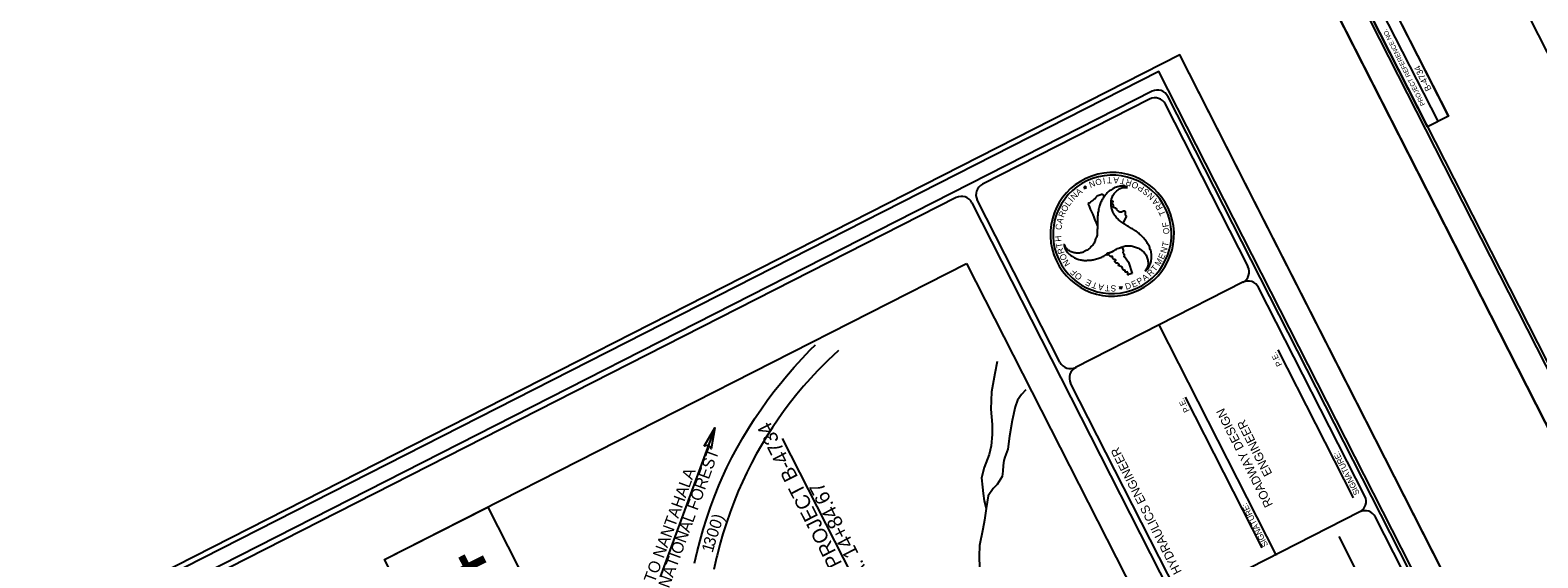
# Model space of a CAD drawing. Extents: x 558484 to 564063, y 513718 to 518374.
# Drawn here: x 558646 to 559932, y 515996 to 516446 of the extents above; entities that cross this region are included whole.
import ezdxf

# ---------------------------------------------------------------- set-up
doc = ezdxf.new("R2010")
doc.units = 0
for name, color, linetype in [('Default', 7, 'Continuous'), ('Prop DSN Text', 7, 'Continuous'), ('Prop Terminator CELL', 7, 'Continuous'), ('Sheet Cutting Line CELL', 7, 'Continuous'), ('Sheet Data Field CELL', 7, 'Continuous'), ('Sheet Plot Border Inside CELL', 7, 'Continuous'), ('Sheet Plot Border Outside CELL', 7, 'Continuous'), ('Sheet Symbology CELL', 7, 'Continuous'), ('Sheet Title CELL', 7, 'Continuous')]:
    doc.layers.add(name, color=color, linetype=linetype)

msp = doc.modelspace()

# ---------------------------------------------------------------- linework, layer by layer
at = {"layer": 'Default'}
msp.add_line((559230, 516106.5), (559183.4, 515979.3), dxfattribs=at)
for points in [[(559444.5, 516246.6), (559867.2, 515416.2), (559371.1, 515163.6), (558948.4, 515994)], [(559036.3, 516038.8), (559079.2, 515954.4), (558991.3, 515909.7), (558948.4, 515994)]]:
    msp.add_lwpolyline(points, close=True, dxfattribs=at)
for points in [[(559212.5, 515991), (559214.8, 516000.7), (559217.3, 516010.3), (559220.1, 516019.8), (559223, 516029.3), (559226.2, 516038.7), (559229.7, 516048), (559233.3, 516057.2), (559236.1, 516063.9), (559240.2, 516072.5), (559244.5, 516081.1), (559249, 516089.5), (559253.7, 516097.8), (559258.6, 516105.9), (559263.8, 516114), (559269.1, 516121.9), (559274.6, 516129.7), (559280.3, 516137.3), (559284.7, 516142.9), (559291.1, 516150.6), (559297.6, 516158.2), (559304.3, 516165.6), (559311.2, 516172.8), (559315.7, 516177.3)], [(559335.3, 516172.3), (559326.2, 516163.7), (559323.6, 516161.3), (559317.4, 516155), (559311.4, 516148.5), (559305.6, 516141.9), (559299.9, 516135.1), (559294.4, 516128.2), (559289.1, 516121.1), (559284, 516113.9), (559279.1, 516106.6), (559274.3, 516099.2), (559269.7, 516091.6), (559265.3, 516083.9), (559261.1, 516076.2), (559257.1, 516068.3), (559253.4, 516060.3), (559249.9, 516052.4), (559246.3, 516043.5), (559243, 516034.4), (559239.8, 516025.3), (559236.9, 516016.1), (559234.2, 516006.9), (559231.8, 515997.6), (559231.4, 515995.9), (559229, 515985.6)], [(559470.6, 516163), (559468.8, 516152.8), (559465.8, 516137.2), (559465.4, 516122.3), (559466.4, 516109.4), (559466.4, 516100.7), (559465.7, 516091.2), (559463.8, 516083.8), (559459.6, 516072.7), (559457.4, 516063.9), (559458.2, 516055.9), (559458.8, 516050.4), (559459.5, 516044.2), (559461.2, 516037.6), (559459.9, 516027.8), (559458.5, 516020.1), (559455.7, 516006.2), (559455.3, 515996.9), (559455.7, 515987)], [(559495.2, 516138.7), (559491.5, 516134.9), (559488.1, 516129.9), (559486, 516124.4), (559483.4, 516112.7), (559481.3, 516099.2), (559479.9, 516088.2), (559477.3, 516081.3), (559476.4, 516078.7), (559475.7, 516074.4), (559475.4, 516069.5), (559474.9, 516064.8), (559470.8, 516058.2), (559467.4, 516054.6), (559462.9, 516048.3), (559461.2, 516037.6)]]:
    msp.add_lwpolyline(points, dxfattribs=at)
at = {"layer": 'Prop DSN Text'}
msp.add_line((559374.5, 515926.8), (559287.7, 516097.2), dxfattribs=at)
at = {"layer": 'Prop Terminator CELL'}
msp.add_lwpolyline([(559220.9, 516090.7), (559230, 516106.5), (559226.8, 516088.4), (559224.6, 516091.7)], close=True, dxfattribs=at)
at = {"layer": 'Sheet Cutting Line CELL'}
for p, q in [((559735.1, 516509.6), (560499.1, 515008.9)), ((560390.4, 514923.8), (559626.4, 516424.4))]:
    msp.add_line(p, q, dxfattribs=at)
at = {"layer": 'Sheet Plot Border Inside CELL'}
for points in [[(561453.5, 515509.4), (560697.4, 516994.5), (559757.1, 516515.8), (560513.2, 515030.7)], [(560364.5, 514925.2), (559608.4, 516410.3), (558668.2, 515931.5), (559424.3, 514446.4)]]:
    msp.add_lwpolyline(points, close=True, dxfattribs=at)
at = {"layer": 'Sheet Plot Border Outside CELL'}
for points in [[(561479.4, 515508), (560715.3, 517008.7), (559735.1, 516509.6), (560499.1, 515008.9)], [(558646.1, 515925.4), (559410.2, 514424.7), (560390.4, 514923.8), (559626.4, 516424.4)]]:
    msp.add_lwpolyline(points, close=True, dxfattribs=at)
at = {"layer": 'Sheet Symbology CELL'}
for p, q in [((559846.6, 516367.8), (559774, 516510.4)), ((559855.5, 516372.3), (559782.9, 516514.9)), ((559924.8, 516455.4), (559998.5, 516310.7))]:
    msp.add_line(p, q, dxfattribs=at)
for points in [[(559765.1, 516505.8), (560445.6, 515169.1), (561380.4, 515645), (560699.9, 516981.8)], [(559837.7, 516363.2), (559765.1, 516505.8), (559782.9, 516514.9), (559855.5, 516372.3)]]:
    msp.add_lwpolyline(points, close=True, dxfattribs=at)
at = {"layer": 'Sheet Title CELL'}
for p, q in [((559551.3, 516321.1), (559551.3, 516321.1)), ((559545.2, 516311.5), (559544.5, 516310.9)), ((559544.5, 516310.9), (559545.4, 516310.9)), ((559545.7, 516311.8), (559544.9, 516312.3)), ((559544.9, 516312.3), (559545.2, 516311.5)), ((559545.4, 516310.9), (559545.7, 516310.1)), ((559546.4, 516312.4), (559545.7, 516311.8)), ((559545.7, 516310.1), (559546, 516311)), ((559546, 516311), (559546.9, 516311)), ((559546.2, 516311.5), (559546.4, 516312.4)), ((559546.9, 516311), (559546.2, 516311.5)), ((560093.5, 515033), (559449.3, 516298.4)), ((559524.2, 516162.3), (559453.7, 516300.7)), ((559581, 516286.8), (559577.9, 516281)), ((559577.9, 516281), (559577.9, 516281)), ((559556.2, 516278.9), (559556.2, 516278.9)), ((559527.6, 516262.8), (559527.7, 516262.7)), ((559527.6, 516262.8), (559527.7, 516262.7)), ((559577.2, 516260.7), (559578.5, 516256.8)), ((559579.3, 516252.4), (559582.8, 516247.6)), ((559582.8, 516247.6), (559585.8, 516238)), ((559680.2, 516230.5), (559537.6, 516157.9)), ((559585.8, 516238), (559582.8, 516237.1)), ((559575, 516225.3), (559575.7, 516225.9)), ((559575.9, 516225.4), (559575, 516225.3)), ((559575.7, 516225.9), (559575.4, 516226.8)), ((559575.4, 516226.8), (559576.1, 516226.2)), ((559576.2, 516224.5), (559575.9, 516225.4)), ((559576.1, 516226.2), (559576.9, 516226.8)), ((559576.4, 516225.4), (559576.2, 516224.5)), ((559577.4, 516225.4), (559576.4, 516225.4)), ((559576.9, 516226.8), (559576.6, 516225.9)), ((559576.6, 516225.9), (559577.4, 516225.4)), ((559709, 515997.6), (559608.9, 516194.2)), ((559774.4, 516046.7), (559710.2, 516172.9)), ((559623.9, 515966.5), (559533.2, 516144.5)), ((559696.7, 516004.1), (559631.3, 516132.7)), ((559779.9, 516034.7), (559637.3, 515962.1)), ((559833.1, 515874.5), (559762.2, 516013.7))]:
    msp.add_line(p, q, dxfattribs=at)
for points in [[(559602.9, 516393.4), (558685, 515926.1)], [(559600.7, 516386.7), (559458.1, 516314.1)], [(559684.6, 516244), (559614.1, 516382.3)], [(560287.8, 515070.1), (559616.3, 516389.1)], [(559435.8, 516302.8), (558691.7, 515923.9)], [(559784.3, 516048.1), (559693.6, 516226.2)], [(559922.7, 515776.3), (559793.4, 516030.3)]]:
    msp.add_lwpolyline(points, dxfattribs=at)
for centre, radius, start, end in [((559605.2, 516377.8), 10, 26.9819, 116.9819), ((559607.4, 516384.5), 10, 26.9819, 116.9819), ((559568.8, 516271.4), 52.7, 109.4031, 289.4031), ((559568.8, 516271.4), 50.5, 109.4031, 289.4031), ((559568.8, 516271.4), 52.7, 289.4031, 109.4031), ((559568.8, 516271.4), 50.5, 289.4031, 109.4031), ((559462.6, 516305.2), 10, 116.9819, 206.9819), ((559440.3, 516293.8), 10, 26.9819, 116.9819), ((559295.9, 516181.4), 277.9, 20.5206, 24.7266), ((559295.9, 516181.4), 277.9, 15.0816, 15.1811), ((559675.6, 516239.4), 10, 296.9819, 26.9819), ((559684.7, 516221.6), 10, 26.9819, 116.9819), ((559533.1, 516166.9), 10, 206.9819, 296.9819), ((559542.2, 516149), 10, 116.9819, 206.9819), ((559775.3, 516043.6), 10, 296.9819, 26.9819), ((559784.4, 516025.8), 10, 26.9819, 116.9819)]:
    msp.add_arc(centre, radius, start, end, dxfattribs=at)
for points in [[(559581.9, 516311.4), (559580.9, 516311.9), (559577.4, 516312.5), (559573.7, 516312), (559573.3, 516311.9), (559571.4, 516311.3), (559569.3, 516310.2), (559565.9, 516308.1), (559563.2, 516305.2), (559562.1, 516304), (559561.1, 516302.4), (559559.3, 516299), (559558, 516295.6), (559557, 516291.5), (559556.4, 516287.8), (559556.3, 516284), (559556.3, 516280.2), (559556.1, 516276.5), (559555.9, 516272.6), (559555.3, 516268.9), (559555.1, 516268.6), (559553.8, 516264.7), (559551.5, 516261.6), (559548.9, 516259), (559547.5, 516258), (559545.5, 516257), (559544.3, 516256.3), (559541.8, 516255.6), (559538, 516255.4), (559534.6, 516256.3), (559531.7, 516257.6), (559529.3, 516259.9), (559527.7, 516262.7), (559527.6, 516262.8)], [(559548.4, 516297.7), (559551.4, 516299.6), (559554.7, 516302.7), (559556.5, 516304.6), (559558.3, 516305.2), (559560.7, 516305.5), (559561.6, 516303.5)], [(559597, 516240.1), (559598, 516240.8), (559600.1, 516243.6), (559601.6, 516247), (559601.7, 516247.3), (559602.1, 516249.3), (559602.3, 516251.7), (559602.1, 516255.6), (559601, 516259.4), (559600.5, 516261), (559599.5, 516262.7), (559597.5, 516265.9), (559595.2, 516268.7), (559592.1, 516271.7), (559589.3, 516274), (559586, 516276), (559582.7, 516278), (559579.6, 516280), (559576.4, 516282.1), (559573.5, 516284.5), (559573.2, 516284.8), (559570.6, 516287.9), (559569, 516291.4), (559568.1, 516294.8), (559567.9, 516296.7), (559568, 516298.9), (559568, 516300.2), (559568.7, 516302.8), (559570.4, 516306.1), (559572.8, 516308.6), (559575.5, 516310.5), (559578.6, 516311.4), (559581.9, 516311.4)], [(559561.7, 516303.5), (559561.1, 516302.4), (559559.3, 516299), (559558, 516295.6), (559557, 516291.5), (559556.4, 516287.8), (559556.3, 516284), (559556.3, 516280.2), (559556.2, 516278.9)], [(559577.9, 516281), (559576.4, 516282.1), (559573.5, 516284.5), (559573.2, 516284.8), (559570.6, 516287.9), (559569, 516291.4), (559568.1, 516294.8), (559567.9, 516296.7), (559568, 516298.9), (559568, 516300.2)], [(559568.1, 516300.1), (559569.1, 516300), (559569.4, 516299.3), (559568.8, 516297.6), (559569.7, 516296.1), (559569.5, 516295.2), (559569.7, 516294.7), (559571.6, 516294.1), (559572.5, 516292.6), (559575.3, 516290.7), (559576.6, 516290.5), (559578.9, 516291.6), (559579.6, 516291.1), (559579.8, 516290.3), (559579.7, 516288.5), (559581, 516286.8)], [(559527.7, 516262.7), (559527.8, 516261.5), (559529.1, 516258.3), (559531.3, 516255.3), (559531.6, 516255), (559533.1, 516253.7), (559535, 516252.4), (559538.5, 516250.6), (559542.4, 516249.6), (559544, 516249.3), (559545.9, 516249.2), (559549.8, 516249.4), (559553.4, 516250), (559557.4, 516251.2), (559560.9, 516252.4), (559564.2, 516254.3), (559567.6, 516256.1), (559570.9, 516257.9), (559574.3, 516259.6), (559577.9, 516260.9), (559578.2, 516261), (559582.2, 516261.7), (559586, 516261.3), (559589.5, 516260.3), (559591.2, 516259.6), (559593.1, 516258.4), (559594.2, 516257.7), (559596.1, 516255.9), (559598.1, 516252.8), (559599.1, 516249.4), (559599.4, 516246.2), (559598.6, 516243), (559597, 516240.1)], [(559564.2, 516254.2), (559564.2, 516254.3), (559567.6, 516256.1), (559570.9, 516257.9), (559574.3, 516259.6), (559577.2, 516260.7)], [(559582.8, 516237.1), (559582.5, 516236.9), (559582, 516237.2), (559582.1, 516238.8), (559581.3, 516239.3), (559580.7, 516239.1), (559579.9, 516239.4), (559579.7, 516240.5), (559578.3, 516241), (559577.8, 516241.7), (559577.3, 516243.4), (559574.5, 516244.6), (559574.1, 516245.4), (559574.6, 516245.8), (559574.5, 516246.4), (559572.6, 516246.7), (559572.2, 516246.8), (559571.1, 516248.1), (559571.2, 516248.7), (559571.9, 516249), (559572, 516249.3), (559571.4, 516249.7), (559570.3, 516250.1), (559569.2, 516251.1), (559568.9, 516252.6), (559567.6, 516252.5), (559565.8, 516253.8), (559565, 516253.9), (559564.3, 516253.7)], [(559578.5, 516256.8), (559577.9, 516256.2), (559578, 516255.3), (559578.9, 516254.5), (559579.1, 516253.7), (559578.8, 516252.6), (559579.3, 516252.4)]]:
    msp.add_spline(points, degree=3, dxfattribs=at)

# ---------------------------------------------------------------- texts
at = {"layer": 'Default'}
for s, height, rotation, p in [('END TIP PROJECT B-4734', 12.5, 116.9819, (559370.7, 515927.9)), ('NATIONAL FOREST', 10, 69.896, (559190.8, 515969.1)), ('TO NANTAHALA', 10, 69.896, (559178.5, 515973.6)), (' -L- STA. 14+84.67', 12.5, 116.9819, (559385.3, 515935.4)), ('0', 10, 70.9744, (559234.1, 516019.4)), (')', 10, 69.5498, (559236.6, 516026.6)), ('3', 10, 73.8277, (559229.5, 516004.7)), ('0', 10, 72.4021, (559231.8, 516012.1)), ('4', 60, 116.9819, (559047.9, 515967)), ('1', 10, 73.8277, (559228, 515999.4))]:
    msp.add_text(s, height=height, rotation=rotation, dxfattribs=at).set_placement(p)
at = {"layer": 'Sheet Data Field CELL'}
msp.add_text('B-4734   ', height=5.4, rotation=116.9819, dxfattribs=at).set_placement((559841.3, 516395.2))
at = {"layer": 'Sheet Symbology CELL'}
msp.add_text('PROJECT REFERENCE NO.', height=4, rotation=116.9819, dxfattribs=at).set_placement((559835.8, 516382.2))
at = {"layer": 'Sheet Title CELL'}
for s, height, rotation, p in [('O', 5.24, 194.3632, (559559.1, 516319.3)), ('I', 5.27, 189.2275, (559562.4, 516319.9)), ('T', 5.25, 183.5776, (559568.3, 516320.3)), ('A', 5.27, 176.4932, (559574.6, 516319.9)), ('T', 5.24, 168.4062, (559580.4, 516318.8)), ('R', 5.26, 162.3064, (559586, 516317.1)), ('N', 5.25, 45.2984, (559536.4, 516300.5)), ('A', 5.26, 37.8664, (559540.1, 516304.2)), ('N', 5.26, 201.6112, (559553, 516317.7)), ('O', 5.27, 155.1173, (559591.8, 516314.5)), ('P', 5.25, 148.4253, (559596.6, 516311.6)), ('S', 5.23, 141.2334, (559601.1, 516308)), ('N', 5.24, 134.023, (559605.4, 516303.8)), ('O', 5.27, 61.2215, (559529.4, 516290)), ('L', 5.24, 54.9878, (559532.1, 516294.9)), ('I', 5.26, 50.9985, (559534.8, 516298.6)), ('A', 5.24, 126.9913, (559609.2, 516298.9)), ('R', 5.26, 120.2382, (559612.2, 516293.9)), ('C', 5.24, 82.2021, (559525.4, 516274.9)), ('A', 5.25, 74.7051, (559526.1, 516280.1)), ('R', 5.25, 68.3411, (559527.5, 516285.3)), ('T', 5.24, 113.2816, (559614.6, 516288.5)), ('F', 5.25, 100.3724, (559617.2, 516278)), ('H', 5.25, 94.5444, (559525.6, 516265.4)), ('O', 5.25, 93.2071, (559617.6, 516271.7)), ('T', 5.27, 101.6292, (559526.6, 516260.4)), ('R', 5.26, 108.2788, (559528.2, 516255.6)), ('O', 5.27, 114.8887, (559530.6, 516250.6)), ('E', 5.24, 66.0899, (559612.5, 516249.6)), ('N', 5.27, 73.0614, (559614.7, 516254.9)), ('T', 5.25, 79.9034, (559616.4, 516260.5)), ('N', 5.26, 122.3868, (559533.3, 516246.2)), ('F', 5.27, 134.4738, (559539.3, 516239.3)), ('R', 5.26, 44.7376, (559601.4, 516235)), ('T', 5.25, 51.3881, (559605.5, 516239.2)), ('M', 5.24, 58.6231, (559609.1, 516243.9)), ('O', 5.26, 141.6206, (559543.7, 516235.9)), ('E', 5.24, 153.56, (559551.8, 516231.3)), ('T', 5.24, 160.6756, (559556.6, 516229.6)), ('A', 5.27, 167.7308, (559562, 516228.4)), ('T', 5.27, 174.7832, (559567.1, 516227.9)), ('S', 5.25, 181.1593, (559572.1, 516228)), ('D', 5.26, 17.2561, (559580.7, 516224.1)), ('E', 5.23, 23.5439, (559586.5, 516225.9)), ('P', 5.26, 31.0763, (559591.7, 516228.3)), ('A', 5.25, 37.6689, (559596.5, 516231.2)), ('P.E.', 5, 116.9819, (559713.9, 516160.3)), ('P.E.', 5, 116.9819, (559634.9, 516121.1)), ('ROADWAY DESIGN', 7.499, 116.9819, (559706, 516040.9)), ('ENGINEER', 7.5, 116.9819, (559705.4, 516067.4)), (' HYDRAULICS ENGINEER', 7.5, 116.9819, (559629.5, 515981.3)), ('SIGNATURE:', 5, 116.9819, (559780, 516050.6)), ('SIGNATURE:', 5, 116.9819, (559701.9, 516006.4))]:
    msp.add_text(s, height=height, rotation=rotation, dxfattribs=at).set_placement(p)

doc.saveas('drawing.dxf')
